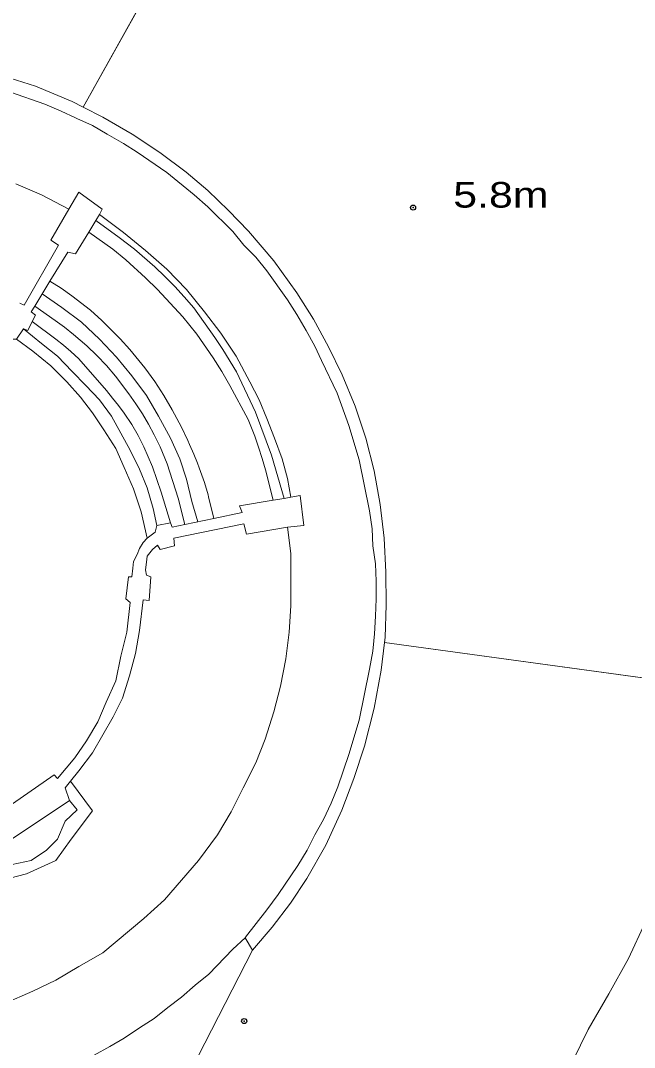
# Model space of a CAD drawing. Extents: x 528790 to 529292, y 179350 to 179856.
# Drawn here: x 529164.2 to 529200.1, y 179712.9 to 179772.9 of the extents above; entities that cross this region are included whole.
import ezdxf

# ---------------------------------------------------------------- set-up
doc = ezdxf.new("R2010")
doc.units = 0
doc.header["$LTSCALE"] = 0.6
doc.header["$PDMODE"] = 32
doc.header["$PDSIZE"] = 0.3
doc.layers.add('1', color=7, linetype='Continuous', lineweight=13)
doc.layers.add('2', color=7, linetype='Continuous', lineweight=13)
doc.layers.add('3', color=7, linetype='Continuous')
doc.layers.add('5', color=7, linetype='Continuous')

msp = doc.modelspace()

# ---------------------------------------------------------------- linework, layer by layer
at = {"layer": '1'}
for points in [[(529140.75, 179788.25), (529142.81, 179769.01), (529144.85, 179769.72), (529146.93, 179770.28), (529148.82, 179770.64), (529150.74, 179770.89), (529152.64, 179771.04), (529154.54, 179771.07), (529156.59, 179770.94), (529158.63, 179770.7), (529160.74, 179770.32), (529162.82, 179769.81), (529165.05, 179769.1), (529167.21, 179768.2), (529167.85, 179767.87), (529177.14, 179784.53)], [(529177.14, 179784.53), (529167.85, 179767.87), (529168.99, 179767.29), (529170.71, 179766.29), (529172.33, 179765.23), (529173.88, 179764.08), (529175.15, 179763), (529176.36, 179761.84), (529177.52, 179760.63), (529179.01, 179758.88), (529180.35, 179757.02), (529181.33, 179755.47), (529182.21, 179753.86), (529183.01, 179752.22), (529183.77, 179750.39), (529184.39, 179748.51), (529184.88, 179746.59), (529185.23, 179744.63), (529185.46, 179742.66), (529185.56, 179740.67), (529185.57, 179738.75), (529185.51, 179736.84), (529185.48, 179736.56), (529204.29, 179733.98)], [(529177.76, 179718.55), (529178.9, 179719.89), (529179.97, 179721.29), (529180.94, 179722.75), (529182.04, 179724.7), (529182.98, 179726.73), (529183.69, 179728.59), (529184.31, 179730.49), (529184.88, 179732.7), (529185.29, 179734.94), (529185.48, 179736.56), (529185.51, 179736.84), (529185.57, 179738.75), (529185.56, 179740.67), (529185.46, 179742.66), (529185.23, 179744.63), (529184.88, 179746.59), (529184.39, 179748.51), (529183.77, 179750.39), (529183.01, 179752.22), (529182.21, 179753.86), (529181.33, 179755.47), (529180.35, 179757.02), (529179.01, 179758.88), (529177.52, 179760.63), (529176.36, 179761.84), (529175.15, 179763), (529173.88, 179764.08), (529172.33, 179765.23), (529170.71, 179766.29), (529168.99, 179767.29), (529167.85, 179767.87), (529167.21, 179768.2), (529165.05, 179769.1), (529162.82, 179769.81)], [(529177.32, 179719.27), (529177.35, 179719.3), (529178.6, 179720.9), (529179.25, 179721.8), (529180.4, 179723.5), (529180.95, 179724.4), (529181.4, 179725.3), (529181.9, 179726.2), (529182.35, 179727.15), (529182.75, 179728.1), (529183.4, 179730), (529184, 179732), (529184.6, 179735), (529184.8, 179736.05), (529184.86, 179736.64), (529184.9, 179737.05), (529184.95, 179738.1), (529185, 179739.1), (529185, 179740.15), (529184.95, 179741.15), (529184.8, 179742.2), (529184.75, 179743.2), (529184.6, 179744.25), (529184, 179747.25), (529183.4, 179749.25), (529182.7, 179751.15), (529181.8, 179753.05), (529181.4, 179753.9), (529180.9, 179754.8), (529180.35, 179755.75), (529179.8, 179756.6), (529178.6, 179758.3), (529177.95, 179759.1), (529177.25, 179759.8), (529176.6, 179760.6), (529175.15, 179762.05), (529174.35, 179762.75), (529172.75, 179764.05), (529171, 179765.25), (529170.2, 179765.75), (529169.25, 179766.3), (529168.4, 179766.8), (529167.48, 179767.21), (529167.4, 179767.25), (529166.55, 179767.65), (529165.6, 179768.05), (529163.6, 179768.75)], [(529163.6, 179768.75), (529165.6, 179768.05), (529166.55, 179767.65), (529167.4, 179767.25), (529167.48, 179767.21), (529168.4, 179766.8), (529169.25, 179766.3), (529170.2, 179765.75), (529171, 179765.25), (529172.75, 179764.05), (529174.35, 179762.75), (529175.15, 179762.05), (529176.6, 179760.6), (529177.25, 179759.8), (529177.95, 179759.1), (529178.6, 179758.3), (529179.8, 179756.6), (529180.35, 179755.75), (529180.9, 179754.8), (529181.4, 179753.9), (529181.8, 179753.05), (529182.7, 179751.15), (529183.4, 179749.25), (529184, 179747.25), (529184.6, 179744.25), (529184.75, 179743.2), (529184.8, 179742.2), (529184.95, 179741.15), (529185, 179740.15), (529185, 179739.1), (529184.95, 179738.1), (529184.9, 179737.05), (529184.86, 179736.64), (529184.8, 179736.05), (529184.6, 179735), (529184, 179732), (529183.4, 179730), (529182.75, 179728.1)], [(529163.9, 179763.4), (529165.4, 179762.75), (529167, 179761.9), (529167.6, 179762.9), (529168.95, 179761.9), (529168.8, 179761.6), (529170.2, 179760.55), (529171.5, 179759.5), (529172.75, 179758.4), (529173.9, 179757.2), (529174.95, 179755.9), (529175.9, 179754.65), (529176.8, 179753.3), (529177.6, 179751.8), (529178.15, 179750.75), (529178.6, 179749.65), (529179.05, 179748.5), (529179.5, 179747.3), (529179.8, 179746.15), (529180, 179745.05), (529180.55, 179745.15), (529180.75, 179743.4), (529179.8, 179743.3), (529180, 179741.75), (529180, 179738.7), (529179.9, 179737.15), (529179.7, 179735.6), (529179.4, 179734), (529179, 179732.5), (529178.5, 179730.9), (529177.95, 179729.5), (529177.2, 179728.05), (529176.5, 179726.65), (529175.7, 179725.3), (529174.6, 179723.8), (529172.6, 179721.5), (529171.4, 179720.4), (529169, 179718.4), (529167.6, 179717.6), (529166.25, 179716.8), (529164.9, 179716.15), (529163.2, 179715.4)], [(529164.15, 179756.4), (529164.4, 179756.3), (529166.4, 179759.8), (529165.95, 179760.1), (529167, 179761.9), (529165.4, 179762.75), (529163.9, 179763.4)], [(529168.173, 179760.57), (529168.587, 179761.25), (529168.8, 179761.6), (529168.95, 179761.9), (529167.6, 179762.9), (529167, 179761.9), (529165.95, 179760.1), (529166.4, 179759.8), (529164.4, 179756.3), (529164.15, 179756.4)], [(529157.4, 179755.6), (529159.5, 179755.05), (529159.35, 179754.7), (529160.5, 179754.25), (529160.7, 179754.6), (529161.5, 179754.3), (529162.2, 179754.15), (529162.8, 179754.2), (529163.35, 179754.3), (529163.95, 179754.3), (529164.35, 179754.9), (529164.6, 179754.8), (529164.86, 179755.33), (529165.05, 179755.7), (529164.8, 179755.9), (529165.01, 179756.24), (529165.9, 179757.7), (529166.95, 179759.4), (529167.4, 179759.3), (529168.173, 179760.57)], [(529160.8, 179725.1), (529166.15, 179728.8), (529166.35, 179728.6), (529167.35, 179729.8), (529168.05, 179730.8), (529168.7, 179731.9), (529169.2, 179733.05), (529169.75, 179734.3), (529170.05, 179735.75), (529170.4, 179737.15), (529170.6, 179738.9), (529170.35, 179739.1), (529170.5, 179740.4), (529170.7, 179740.4), (529170.75, 179740.9), (529170.8, 179741.3), (529171, 179741.7), (529171.15, 179742.05), (529171.35, 179742.4), (529171.6, 179742.65), (529171.25, 179744.2), (529170.8, 179745.55), (529170.25, 179746.8), (529169.75, 179747.9), (529169.05, 179749), (529168.4, 179750), (529167.7, 179750.9), (529166.9, 179751.8), (529165.95, 179752.75), (529164.9, 179753.6), (529163.95, 179754.3)], [(529180.55, 179745.15), (529180, 179745.05), (529179.607, 179744.984), (529178.958, 179744.876), (529177, 179744.55), (529177.15, 179744.15), (529175.5, 179743.81), (529173.79, 179743.45), (529173.05, 179743.3), (529172.95, 179743.55), (529172.15, 179743.4), (529172.05, 179743), (529171.6, 179742.65), (529171.35, 179742.4), (529171.15, 179742.05), (529171, 179741.7), (529170.8, 179741.3), (529170.75, 179740.9), (529170.7, 179740.4), (529170.5, 179740.4), (529170.35, 179739.1), (529170.6, 179738.9), (529170.4, 179737.15), (529170.05, 179735.75), (529169.75, 179734.3), (529169.2, 179733.05), (529168.7, 179731.9), (529168.05, 179730.8), (529167.35, 179729.8), (529166.35, 179728.6), (529166.15, 179728.8), (529160.8, 179725.1)], [(529171.7, 179739), (529171.8, 179740.4), (529171.55, 179740.5), (529171.5, 179740.8), (529171.55, 179741.25), (529171.6, 179741.6), (529171.9, 179742), (529172.2, 179742.25), (529172.35, 179742), (529173.2, 179742.2), (529173.15, 179742.65), (529177.25, 179743.5), (529177.4, 179742.9), (529179.8, 179743.3), (529180.75, 179743.4), (529180.55, 179745.15)], [(529163.2, 179715.4), (529164.9, 179716.15), (529166.25, 179716.8), (529167.6, 179717.6), (529169, 179718.4), (529171.4, 179720.4), (529172.6, 179721.5), (529174.6, 179723.8), (529175.7, 179725.3), (529176.5, 179726.65), (529177.2, 179728.05), (529177.95, 179729.5), (529178.5, 179730.9), (529179, 179732.5), (529179.4, 179734), (529179.7, 179735.6), (529179.9, 179737.15), (529180, 179738.7), (529180, 179741.75), (529179.8, 179743.3), (529177.4, 179742.9), (529177.25, 179743.5), (529173.15, 179742.65), (529173.2, 179742.2), (529172.35, 179742), (529172.2, 179742.25), (529171.9, 179742), (529171.6, 179741.6), (529171.55, 179741.25), (529171.5, 179740.8), (529171.55, 179740.5), (529171.8, 179740.4), (529171.7, 179739), (529171.35, 179739.05), (529171.15, 179737.25), (529170.9, 179735.9), (529170.55, 179734.6), (529170.15, 179733.3), (529169.6, 179732.2), (529168.4, 179730.1), (529167.6, 179729.05), (529167.115, 179728.444), (529168.4, 179726.7), (529167.147, 179725.041), (529166.25, 179723.8), (529164.54, 179723.007), (529161.75, 179722.3)], [(529161.7, 179723.75), (529167.05, 179727.3), (529166.8, 179728.05), (529167.115, 179728.444), (529167.6, 179729.05), (529168.4, 179730.1), (529169.6, 179732.2), (529170.15, 179733.3), (529170.55, 179734.6), (529170.9, 179735.9), (529171.15, 179737.25), (529171.35, 179739.05), (529171.7, 179739)], [(529204.29, 179733.98), (529185.48, 179736.56), (529185.29, 179734.94), (529184.88, 179732.7), (529184.31, 179730.49), (529183.69, 179728.59), (529182.98, 179726.73), (529182.04, 179724.7), (529180.94, 179722.75), (529179.97, 179721.29), (529178.9, 179719.89), (529177.76, 179718.55), (529164.6, 179692.9), (529149.59, 179660.85)], [(529182.75, 179728.1), (529182.35, 179727.15), (529181.9, 179726.2), (529181.4, 179725.3), (529180.95, 179724.4), (529180.4, 179723.5), (529179.25, 179721.8), (529178.6, 179720.9), (529177.35, 179719.3), (529177.32, 179719.27), (529177.76, 179718.55)], [(529200.75, 179720.2), (529199.75, 179718.05), (529198.6, 179716), (529197.4, 179713.9), (529195.2, 179709.4), (529194.75, 179708.3), (529194.35, 179707.15), (529194.14, 179706.28), (529194.05, 179705.9), (529193.95, 179704.9), (529193.8, 179703.8), (529193.8, 179702.8), (529193.84, 179702.45), (529193.95, 179701.4), (529194.2, 179700), (529194.9, 179698.3), (529195.25, 179697.6), (529206.95, 179680.56)], [(529195.2, 179709.4), (529197.4, 179713.9), (529198.6, 179716), (529199.75, 179718.05), (529200.75, 179720.2)], [(529164.6, 179692.9), (529177.76, 179718.55), (529177.32, 179719.27), (529176.6, 179718.6), (529175.2, 179717.15), (529174.4, 179716.5), (529173.6, 179715.8), (529172.8, 179715.2), (529172, 179714.55), (529171.15, 179714), (529170.25, 179713.4), (529169.4, 179712.9), (529168.5, 179712.4)], [(529168.5, 179712.4), (529169.4, 179712.9), (529170.25, 179713.4), (529171.15, 179714), (529172, 179714.55), (529172.8, 179715.2), (529173.6, 179715.8), (529174.4, 179716.5), (529175.2, 179717.15), (529176.6, 179718.6), (529177.32, 179719.27)]]:
    msp.add_lwpolyline(points, dxfattribs=at)
for points in [[(529179.607, 179744.984), (529178.87, 179747.513), (529177.922, 179750.038), (529176.811, 179752.39), (529176.021, 179753.692), (529175.55, 179754.4), (529174.313, 179756.127), (529173.762, 179756.782), (529173.209, 179757.386), (529172.633, 179757.969), (529172.039, 179758.534), (529170.849, 179759.567), (529169.95, 179760.25), (529168.587, 179761.25), (529168.173, 179760.57), (529169.576, 179759.559), (529170.339, 179758.943), (529171.503, 179757.889), (529172.2, 179757.2), (529173.681, 179755.609), (529174.5, 179754.6), (529175.462, 179753.213), (529175.958, 179752.411), (529176.435, 179751.597), (529177.5, 179749.6), (529177.89, 179748.634), (529178.113, 179747.982), (529178.318, 179747.324), (529178.51, 179746.662), (529178.958, 179744.876)], [(529180, 179745.05), (529179.8, 179746.15), (529179.5, 179747.3), (529179.05, 179748.5), (529178.6, 179749.65), (529178.15, 179750.75), (529177.6, 179751.8), (529176.8, 179753.3), (529175.9, 179754.65), (529174.95, 179755.9), (529173.9, 179757.2), (529172.75, 179758.4), (529171.5, 179759.5), (529170.2, 179760.55), (529168.8, 179761.6), (529168.587, 179761.25), (529169.95, 179760.25), (529170.849, 179759.567), (529172.039, 179758.534), (529172.633, 179757.969), (529173.209, 179757.386), (529173.762, 179756.782), (529174.313, 179756.127), (529175.55, 179754.4), (529176.021, 179753.692), (529176.811, 179752.39), (529177.922, 179750.038), (529178.87, 179747.513), (529179.607, 179744.984)], [(529169.576, 179759.559), (529168.173, 179760.57), (529167.4, 179759.3), (529166.95, 179759.4), (529165.9, 179757.7), (529166.553, 179757.284), (529167.189, 179756.841), (529168.267, 179755.998), (529168.948, 179755.393), (529170.01, 179754.33), (529170.577, 179753.704), (529171.463, 179752.617), (529172.033, 179751.825), (529172.563, 179751.006), (529173.057, 179750.165), (529173.595, 179749.15), (529173.973, 179748.368), (529174.076, 179748.134), (529174.324, 179747.573), (529174.535, 179747.039), (529174.643, 179746.765), (529174.939, 179745.914), (529175.152, 179745.201), (529175.188, 179745.082), (529175.5, 179743.81), (529177.15, 179744.15), (529177, 179744.55), (529178.958, 179744.876), (529178.51, 179746.662), (529178.318, 179747.324), (529178.113, 179747.982), (529177.89, 179748.634), (529177.5, 179749.6), (529176.435, 179751.597), (529175.958, 179752.411), (529175.462, 179753.213), (529174.5, 179754.6), (529173.681, 179755.609), (529172.2, 179757.2), (529171.503, 179757.889), (529170.339, 179758.943)], [(529168.948, 179755.393), (529168.267, 179755.998), (529167.189, 179756.841), (529166.553, 179757.284), (529165.9, 179757.7), (529165.01, 179756.24), (529164.8, 179755.9), (529165.05, 179755.7), (529164.86, 179755.33), (529164.6, 179754.8), (529164.35, 179754.9), (529163.95, 179754.3), (529164.9, 179753.6), (529165.95, 179752.75), (529166.9, 179751.8), (529167.7, 179750.9), (529168.4, 179750), (529169.05, 179749), (529169.75, 179747.9), (529170.25, 179746.8), (529170.8, 179745.55), (529171.25, 179744.2), (529171.6, 179742.65), (529172.05, 179743), (529172.15, 179743.4), (529172.95, 179743.55), (529173.05, 179743.3), (529173.79, 179743.45), (529175.5, 179743.81), (529175.188, 179745.082), (529175.152, 179745.201), (529174.939, 179745.914), (529174.643, 179746.765), (529174.535, 179747.039), (529174.324, 179747.573), (529174.076, 179748.134), (529173.973, 179748.368), (529173.595, 179749.15), (529173.057, 179750.165), (529172.563, 179751.006), (529172.033, 179751.825), (529171.463, 179752.617), (529170.577, 179753.704), (529170.01, 179754.33)], [(529166.25, 179723.8), (529167.147, 179725.041), (529168.4, 179726.7), (529167.115, 179728.444), (529166.8, 179728.05), (529167.05, 179727.3), (529167.5, 179726.75), (529166.8, 179726.1), (529166.35, 179725.05), (529165.7, 179724.4), (529164.8, 179723.8), (529162.2, 179723.25), (529161.7, 179723.75), (529161.35, 179724.2), (529160.551, 179723.865), (529161.75, 179722.3), (529164.54, 179723.007)], [(529164.8, 179723.8), (529165.7, 179724.4), (529166.35, 179725.05), (529166.8, 179726.1), (529167.5, 179726.75), (529167.05, 179727.3), (529161.7, 179723.75), (529162.2, 179723.25)]]:
    msp.add_lwpolyline(points, close=True, dxfattribs=at)
at = {"layer": '2'}
for p, q in [((529177.14, 179784.53), (529167.85, 179767.87)), ((529168.587, 179761.25), (529168.173, 179760.57)), ((529168.8, 179761.6), (529168.587, 179761.25)), ((529178.958, 179744.876), (529179.607, 179744.984)), ((529179.607, 179744.984), (529180, 179745.05)), ((529204.29, 179733.98), (529185.48, 179736.56)), ((529167.05, 179727.3), (529161.7, 179723.75)), ((529177.32, 179719.27), (529177.76, 179718.55))]:
    msp.add_line(p, q, dxfattribs=at)
for points in [[(529142.81, 179769.01), (529144.85, 179769.72), (529146.93, 179770.28), (529148.82, 179770.64), (529150.74, 179770.89), (529152.64, 179771.04), (529154.54, 179771.07), (529156.59, 179770.94), (529158.63, 179770.7), (529160.74, 179770.32), (529162.82, 179769.81), (529165.05, 179769.1), (529167.21, 179768.2), (529167.85, 179767.87)], [(529177.32, 179719.27), (529177.35, 179719.3), (529178.6, 179720.9), (529179.25, 179721.8), (529180.4, 179723.5), (529180.95, 179724.4), (529181.4, 179725.3), (529181.9, 179726.2), (529182.35, 179727.15), (529182.75, 179728.1), (529183.4, 179730), (529184, 179732), (529184.6, 179735), (529184.8, 179736.05), (529184.86, 179736.64), (529184.9, 179737.05), (529184.95, 179738.1), (529185, 179739.1), (529185, 179740.15), (529184.95, 179741.15), (529184.8, 179742.2), (529184.75, 179743.2), (529184.6, 179744.25), (529184, 179747.25), (529183.4, 179749.25), (529182.7, 179751.15), (529181.8, 179753.05), (529181.4, 179753.9), (529180.9, 179754.8), (529180.35, 179755.75), (529179.8, 179756.6), (529178.6, 179758.3), (529177.95, 179759.1), (529177.25, 179759.8), (529176.6, 179760.6), (529175.15, 179762.05), (529174.35, 179762.75), (529172.75, 179764.05), (529171, 179765.25), (529170.2, 179765.75), (529169.25, 179766.3), (529168.4, 179766.8), (529167.48, 179767.21), (529167.4, 179767.25), (529166.55, 179767.65), (529165.6, 179768.05), (529163.6, 179768.75)], [(529167.85, 179767.87), (529168.99, 179767.29), (529170.71, 179766.29), (529172.33, 179765.23), (529173.88, 179764.08), (529175.15, 179763), (529176.36, 179761.84), (529177.52, 179760.63), (529179.01, 179758.88), (529180.35, 179757.02), (529181.33, 179755.47), (529182.21, 179753.86), (529183.01, 179752.22), (529183.77, 179750.39), (529184.39, 179748.51), (529184.88, 179746.59), (529185.23, 179744.63), (529185.46, 179742.66), (529185.56, 179740.67), (529185.57, 179738.75), (529185.51, 179736.84), (529185.48, 179736.56)], [(529163.9, 179763.4), (529165.4, 179762.75), (529167, 179761.9)], [(529168.8, 179761.6), (529168.95, 179761.9), (529167.6, 179762.9), (529167, 179761.9)], [(529164.15, 179756.4), (529164.4, 179756.3), (529166.4, 179759.8), (529165.95, 179760.1), (529167, 179761.9)], [(529168.587, 179761.25), (529169.95, 179760.25), (529170.849, 179759.567), (529172.039, 179758.534), (529172.633, 179757.969), (529173.209, 179757.386), (529173.762, 179756.782), (529174.313, 179756.127), (529175.55, 179754.4), (529176.021, 179753.692), (529176.811, 179752.39), (529177.922, 179750.038), (529178.87, 179747.513), (529179.607, 179744.984)], [(529168.8, 179761.6), (529170.2, 179760.55), (529171.5, 179759.5), (529172.75, 179758.4), (529173.9, 179757.2), (529174.95, 179755.9), (529175.9, 179754.65), (529176.8, 179753.3), (529177.6, 179751.8), (529178.15, 179750.75), (529178.6, 179749.65), (529179.05, 179748.5), (529179.5, 179747.3), (529179.8, 179746.15), (529180, 179745.05)], [(529168.173, 179760.57), (529167.4, 179759.3), (529166.95, 179759.4), (529165.9, 179757.7)], [(529178.958, 179744.876), (529178.51, 179746.662), (529178.318, 179747.324), (529178.113, 179747.982), (529177.89, 179748.634), (529177.5, 179749.6), (529176.435, 179751.597), (529175.958, 179752.411), (529175.462, 179753.213), (529174.5, 179754.6), (529173.681, 179755.609), (529172.2, 179757.2), (529171.503, 179757.889), (529170.339, 179758.943), (529169.576, 179759.559), (529168.173, 179760.57)], [(529165.9, 179757.7), (529165.01, 179756.24), (529164.8, 179755.9), (529165.05, 179755.7), (529164.86, 179755.33), (529164.6, 179754.8), (529164.35, 179754.9), (529163.95, 179754.3)], [(529165.9, 179757.7), (529166.553, 179757.284), (529167.189, 179756.841), (529168.267, 179755.998), (529168.948, 179755.393), (529170.01, 179754.33), (529170.577, 179753.704), (529171.463, 179752.617), (529172.033, 179751.825), (529172.563, 179751.006), (529173.057, 179750.165), (529173.595, 179749.15), (529173.973, 179748.368), (529174.076, 179748.134), (529174.324, 179747.573), (529174.535, 179747.039), (529174.643, 179746.765), (529174.939, 179745.914), (529175.152, 179745.201), (529175.188, 179745.082), (529175.5, 179743.81)], [(529165.45, 179756.96), (529166.6, 179756.15), (529167.75, 179755.3), (529168.8, 179754.3), (529169.8, 179753.25), (529170.7, 179752.15), (529171.55, 179751), (529172.25, 179749.8), (529172.95, 179748.5), (529173.5, 179747.3), (529173.9, 179746.1), (529174.2, 179744.8), (529174.55, 179743.61)], [(529165.01, 179756.24), (529166.2, 179755.4), (529166.745, 179754.996), (529167.283, 179754.583), (529168.07, 179753.918), (529168.653, 179753.352), (529169.207, 179752.757), (529169.733, 179752.137), (529170.524, 179751.098), (529170.926, 179750.519), (529171.309, 179749.927), (529171.671, 179749.321), (529172.008, 179748.702), (529172.35, 179748), (529172.759, 179747.006), (529173.4, 179745), (529173.79, 179743.45)], [(529164.86, 179755.33), (529166.25, 179754.3), (529166.693, 179753.945), (529167.128, 179753.581), (529167.6, 179753.15), (529169.209, 179751.289), (529169.561, 179750.853), (529169.911, 179750.414), (529170.249, 179749.967), (529170.7, 179749.3), (529171.066, 179748.662), (529171.396, 179748.005), (529171.899, 179746.836), (529172.414, 179745.349), (529172.95, 179743.55)], [(529164.35, 179754.9), (529165.4, 179754.05), (529166.35, 179753.3), (529167.2, 179752.4), (529168, 179751.6), (529168.8, 179750.75), (529169.5, 179749.8), (529170.6, 179747.8), (529171.15, 179746.7), (529171.6, 179745.6), (529171.95, 179744.4), (529172.15, 179743.4)], [(529163.95, 179754.3), (529164.9, 179753.6), (529165.95, 179752.75), (529166.9, 179751.8), (529167.7, 179750.9), (529168.4, 179750), (529169.05, 179749), (529169.75, 179747.9), (529170.25, 179746.8), (529170.8, 179745.55), (529171.25, 179744.2), (529171.6, 179742.65)], [(529175.5, 179743.81), (529177.15, 179744.15), (529177, 179744.55), (529178.958, 179744.876)], [(529179.8, 179743.3), (529180.75, 179743.4), (529180.55, 179745.15), (529180, 179745.05)], [(529171.6, 179742.65), (529172.05, 179743), (529172.15, 179743.4), (529172.95, 179743.55), (529173.05, 179743.3), (529173.79, 179743.45), (529175.5, 179743.81)], [(529179.8, 179743.3), (529180, 179741.75), (529180, 179738.7), (529179.9, 179737.15), (529179.7, 179735.6), (529179.4, 179734), (529179, 179732.5), (529178.5, 179730.9), (529177.95, 179729.5), (529177.2, 179728.05), (529176.5, 179726.65), (529175.7, 179725.3), (529174.6, 179723.8), (529172.6, 179721.5), (529171.4, 179720.4), (529169, 179718.4), (529167.6, 179717.6), (529166.25, 179716.8), (529164.9, 179716.15), (529163.2, 179715.4)], [(529179.8, 179743.3), (529177.4, 179742.9), (529177.25, 179743.5), (529173.15, 179742.65), (529173.2, 179742.2), (529172.35, 179742), (529172.2, 179742.25), (529171.9, 179742), (529171.6, 179741.6), (529171.55, 179741.25), (529171.5, 179740.8), (529171.55, 179740.5), (529171.8, 179740.4), (529171.7, 179739), (529171.35, 179739.05), (529171.15, 179737.25), (529170.9, 179735.9), (529170.55, 179734.6), (529170.15, 179733.3), (529169.6, 179732.2), (529168.4, 179730.1), (529167.6, 179729.05), (529167.115, 179728.444)], [(529160.8, 179725.1), (529166.15, 179728.8), (529166.35, 179728.6), (529167.35, 179729.8), (529168.05, 179730.8), (529168.7, 179731.9), (529169.2, 179733.05), (529169.75, 179734.3), (529170.05, 179735.75), (529170.4, 179737.15), (529170.6, 179738.9), (529170.35, 179739.1), (529170.5, 179740.4), (529170.7, 179740.4), (529170.75, 179740.9), (529170.8, 179741.3), (529171, 179741.7), (529171.15, 179742.05), (529171.35, 179742.4), (529171.6, 179742.65)], [(529185.48, 179736.56), (529185.29, 179734.94), (529184.88, 179732.7), (529184.31, 179730.49), (529183.69, 179728.59), (529182.98, 179726.73), (529182.04, 179724.7), (529180.94, 179722.75), (529179.97, 179721.29), (529178.9, 179719.89), (529177.76, 179718.55)], [(529167.115, 179728.444), (529168.4, 179726.7), (529167.147, 179725.041), (529166.25, 179723.8), (529164.54, 179723.007), (529161.75, 179722.3), (529160.551, 179723.865)], [(529167.115, 179728.444), (529166.8, 179728.05), (529167.05, 179727.3)], [(529167.05, 179727.3), (529167.5, 179726.75), (529166.8, 179726.1), (529166.35, 179725.05), (529165.7, 179724.4), (529164.8, 179723.8), (529162.2, 179723.25), (529161.7, 179723.75)], [(529206.95, 179680.56), (529195.25, 179697.6), (529194.9, 179698.3), (529194.2, 179700), (529193.95, 179701.4), (529193.84, 179702.45), (529193.8, 179702.8), (529193.8, 179703.8), (529193.95, 179704.9), (529194.05, 179705.9), (529194.14, 179706.28), (529194.35, 179707.15), (529194.75, 179708.3), (529195.2, 179709.4), (529197.4, 179713.9), (529198.6, 179716), (529199.75, 179718.05), (529200.75, 179720.2)], [(529168.5, 179712.4), (529169.4, 179712.9), (529170.25, 179713.4), (529171.15, 179714), (529172, 179714.55), (529172.8, 179715.2), (529173.6, 179715.8), (529174.4, 179716.5), (529175.2, 179717.15), (529176.6, 179718.6), (529177.32, 179719.27)], [(529177.76, 179718.55), (529164.6, 179692.9), (529149.59, 179660.85)]]:
    msp.add_lwpolyline(points, dxfattribs=at)
at = {"layer": '3'}
for p in [(529187.15, 179762), (529177.27, 179714.4)]:
    msp.add_point(p, dxfattribs=at)

# ---------------------------------------------------------------- texts
at = {"layer": '5', "width": 1.25}
msp.add_text('5.8m', height=1.5, dxfattribs=at).set_placement((529189.5, 179762))

doc.saveas('drawing.dxf')
